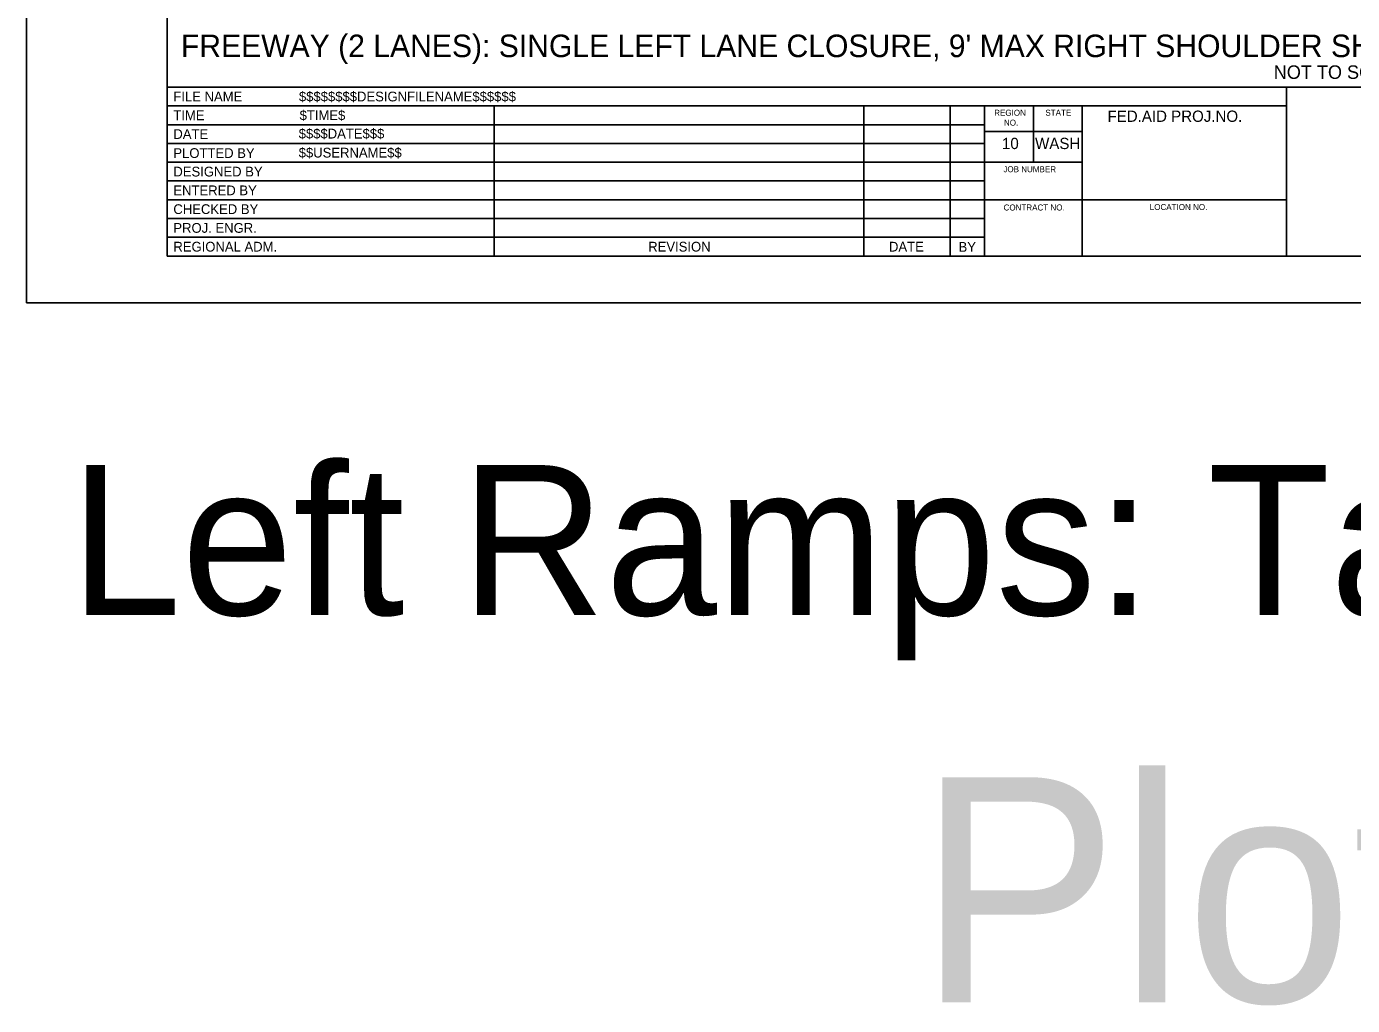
# Model space of a CAD drawing. Extents: x 99999 to 100116, y 99995 to 100013.
# Drawn here: x 100079.06 to 100087.9, y 99995.01 to 100001.53 of the extents above; entities that cross this region are included whole.
import ezdxf

# ---------------------------------------------------------------- set-up
doc = ezdxf.new("R2010")
doc.units = 0
for name, color, linetype in [('SH_DE_DetailHeading1Text', 7, 'Continuous'), ('SH_GI_PlotLimits', 7, 'Continuous'), ('SH_GI_SheetBorder', 7, 'Continuous'), ('SH_GI_SheetLocationText', 7, 'Continuous'), ('SH_GI_SheetTextInCells', 7, 'Continuous'), ('SH_GI_TitleBlockText', 7, 'Continuous')]:
    doc.layers.add(name, color=color, linetype=linetype)

msp = doc.modelspace()

# ---------------------------------------------------------------- linework, layer by layer
at = {"layer": 'SH_GI_PlotLimits'}
msp.add_lwpolyline([(100079.0625, 99999.6875), (100096.0625, 99999.6875), (100096.0625, 100010.6875), (100079.0625, 100010.6875)], close=True, dxfattribs=at)
at = {"layer": 'SH_GI_SheetBorder'}
for p, q in [((100080, 100010.375), (100080, 100000)), ((100080, 100001.1259), (100095.75, 100001.1259)), ((100087.4566, 100000), (100087.4566, 100001.1259)), ((100080, 100001.0008), (100087.4566, 100001.0008)), ((100082.179, 100001.0008), (100082.179, 100000)), ((100084.641, 100001.0008), (100084.641, 100000)), ((100085.2164, 100001.0008), (100085.2164, 100000)), ((100085.4451, 100001.0008), (100085.4451, 100000)), ((100085.7719, 100000.6255), (100085.7719, 100001.0008)), ((100086.0956, 100000), (100086.0956, 100001.0008)), ((100080, 100000.8757), (100082.1821, 100000.8757)), ((100082.1821, 100000.8757), (100085.4466, 100000.8757)), ((100080, 100000.7506), (100082.1821, 100000.7506)), ((100082.1821, 100000.7506), (100085.4466, 100000.7506)), ((100086.0958, 100000.831), (100085.4466, 100000.831)), ((100080, 100000.6255), (100085.4466, 100000.6255)), ((100086.0958, 100000.6255), (100085.4466, 100000.6255)), ((100080, 100000.5004), (100085.4466, 100000.5004)), ((100080, 100000.3753), (100085.4466, 100000.3753)), ((100087.4566, 100000.3753), (100085.4466, 100000.3753)), ((100080, 100000.2502), (100085.4466, 100000.2502)), ((100080, 100000.1251), (100085.4466, 100000.1251)), ((100080, 100000), (100095.75, 100000))]:
    msp.add_line(p, q, dxfattribs=at)

# ---------------------------------------------------------------- texts
at = {"layer": 'SH_DE_DetailHeading1Text'}
for s, height, p in [("FREEWAY (2 LANES): SINGLE LEFT LANE CLOSURE, 9' MAX RIGHT SHOULDER SHIFT (45 MPH WORK ZONE SPEED LIMIT, 40 MPH ADVISORY SPEED)", 0.15, (100080.0913, 100001.3259)), ('NOT TO SCALE', 0.09, (100087.3727, 100001.1809))]:
    msp.add_text(s, height=height, rotation=360, dxfattribs=at).set_placement(p)
at = {"layer": 'SH_GI_SheetLocationText'}
for s, height, p in [('Left Ramps: Tapered On-Ramp', 1, (100079.3513, 99997.6071)), ('Plot 5', 1.5, (100085.0007, 99995.0267))]:
    msp.add_text(s, height=height, dxfattribs=at).set_placement(p)
at = {"layer": 'SH_GI_SheetTextInCells'}
for s, height, p in [('FILE NAME', 0.06505, (100080.041, 100001.0308)), ('TIME', 0.06505, (100080.041, 100000.9057)), ('REGION', 0.04003, (100085.5099, 100000.9352)), ('STATE', 0.04003, (100085.8511, 100000.9357)), ('FED.AID PROJ.NO.', 0.07506, (100086.2652, 100000.8945)), ('DATE', 0.06505, (100080.041, 100000.7806)), ('NO.', 0.04003, (100085.5752, 100000.869)), ('10', 0.07506, (100085.5621, 100000.7131)), ('WASH', 0.07506, (100085.7826, 100000.7131)), ('PLOTTED BY', 0.06505, (100080.041, 100000.6538)), ('DESIGNED BY', 0.065052, (100080.041, 100000.5304)), ('JOB NUMBER', 0.04003, (100085.5712, 100000.5587)), ('ENTERED BY', 0.06505, (100080.041, 100000.4053)), ('CHECKED BY', 0.06505, (100080.041, 100000.2802)), ('CONTRACT NO.', 0.040032, (100085.5725, 100000.3037)), ('LOCATION NO.', 0.040032, (100086.5465, 100000.3067)), ('PROJ. ENGR.', 0.065052, (100080.041, 100000.1551)), ('REGIONAL ADM.', 0.065052, (100080.041, 100000.03)), ('REVISION', 0.06505, (100083.2048, 100000.03)), ('DATE', 0.06505, (100084.8091, 100000.03)), ('BY', 0.06505, (100085.2725, 100000.0285))]:
    msp.add_text(s, height=height, dxfattribs=at).set_placement(p)
at = {"layer": 'SH_GI_TitleBlockText'}
for s, height, p in [('$$$$$$$$DESIGNFILENAME$$$$$$', 0.065052, (100080.8775, 100001.0308)), ('$TIME$', 0.06505, (100080.882, 100000.9059)), ('$$$$DATE$$$', 0.065052, (100080.8759, 100000.7835)), ('$$USERNAME$$', 0.065052, (100080.8759, 100000.6567))]:
    msp.add_text(s, height=height, dxfattribs=at).set_placement(p)

doc.saveas('drawing.dxf')
